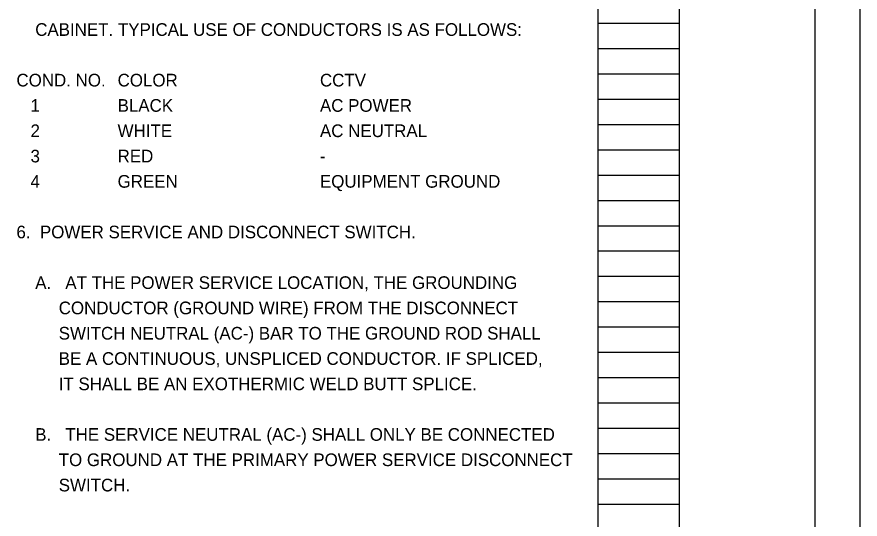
# Model space of a CAD drawing. Extents: x 0 to 34, y 0 to 22.
# Drawn here: x 24.66 to 34, y 5.57 to 11.13 of the extents above; entities that cross this region are included whole.
import ezdxf

# ---------------------------------------------------------------- set-up
doc = ezdxf.new("R2010")
doc.units = 0
for name, color, linetype in [('SH_Border', 7, 'Continuous'), ('SH_Cut_Line', 7, 'Continuous'), ('SH_Data', 7, 'Continuous'), ('SH_Text', 7, 'Continuous')]:
    doc.layers.add(name, color=color, linetype=linetype)

msp = doc.modelspace()

# ---------------------------------------------------------------- linework, layer by layer
at = {"layer": 'SH_Border'}
msp.add_line((32, 0.5), (32, 21.5), dxfattribs=at)
msp.add_lwpolyline([(1.5, 21.5), (33.5, 21.5), (33.5, 0.5), (1.5, 0.5)], close=True, dxfattribs=at)
at = {"layer": 'SH_Cut_Line'}
msp.add_lwpolyline([(0, 0), (34, 0), (34, 22), (0, 22)], close=True, dxfattribs=at)
at = {"layer": 'SH_Data'}
for p, q in [((31.1, 0.98), (31.1, 21.14)), ((32, 0.98), (32, 21.14)), ((31.1, 11.06), (32, 11.06)), ((31.1, 10.78), (32, 10.78)), ((31.1, 10.5), (32, 10.5)), ((31.1, 10.22), (32, 10.22)), ((31.1, 9.94), (32, 9.94)), ((31.1, 9.66), (32, 9.66)), ((31.1, 9.38), (32, 9.38)), ((31.1, 9.1), (32, 9.1)), ((31.1, 8.82), (32, 8.82)), ((31.1, 8.54), (32, 8.54)), ((31.1, 8.26), (32, 8.26)), ((31.1, 7.98), (32, 7.98)), ((31.1, 7.7), (32, 7.7)), ((31.1, 7.42), (32, 7.42)), ((31.1, 7.14), (32, 7.14)), ((31.1, 6.86), (32, 6.86)), ((31.1, 6.58), (32, 6.58)), ((31.1, 6.3), (32, 6.3)), ((31.1, 6.02), (32, 6.02)), ((31.1, 5.74), (32, 5.74))]:
    msp.add_line(p, q, dxfattribs=at)

# ---------------------------------------------------------------- texts
at = {"layer": 'SH_Text'}
for s, p in [('    CABINET. TYPICAL USE OF CONDUCTORS IS AS FOLLOWS:', (24.66, 10.92)), ('COND. NO.', (24.66, 10.36)), ('COLOR', (25.78, 10.36)), ('CCTV      ', (28.02, 10.36)), ('   1', (24.66, 10.08)), ('BLACK', (25.78, 10.08)), ('AC POWER', (28.02, 10.08)), ('   2 ', (24.66, 9.8)), ('WHITE', (25.78, 9.8)), ('AC NEUTRAL', (28.02, 9.8)), ('   3', (24.66, 9.52)), ('RED', (25.78, 9.52)), ('-', (28.02, 9.52)), ('   4', (24.66, 9.24)), ('GREEN ', (25.78, 9.24)), ('EQUIPMENT GROUND', (28.02, 9.24)), ('6.  POWER SERVICE AND DISCONNECT SWITCH.', (24.66, 8.68)), ('    A.   AT THE POWER SERVICE LOCATION, THE GROUNDING', (24.66, 8.12)), ('         CONDUCTOR (GROUND WIRE) FROM THE DISCONNECT', (24.66, 7.84)), ('         SWITCH NEUTRAL (AC-) BAR TO THE GROUND ROD SHALL', (24.66, 7.56)), ('         BE A CONTINUOUS, UNSPLICED CONDUCTOR. IF SPLICED,', (24.66, 7.28)), ('         IT SHALL BE AN EXOTHERMIC WELD BUTT SPLICE.', (24.66, 7)), ('    B.   THE SERVICE NEUTRAL (AC-) SHALL ONLY BE CONNECTED', (24.66, 6.44)), ('         TO GROUND AT THE PRIMARY POWER SERVICE DISCONNECT', (24.66, 6.16)), ('         SWITCH.', (24.66, 5.88))]:
    msp.add_text(s, height=0.14, dxfattribs=at).set_placement(p)

doc.saveas('drawing.dxf')
